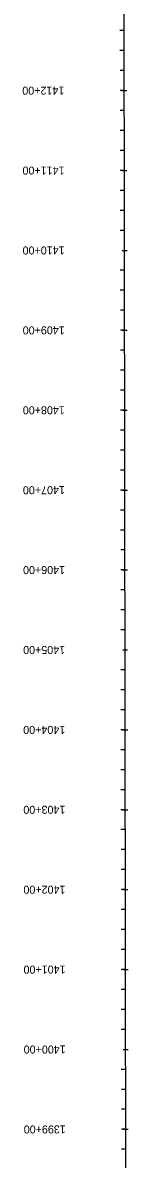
# Model space of a CAD drawing. Extents: x 14541681 to 14544384, y 8572153 to 8583558.
# Drawn here: x 14541682 to 14541814, y 8580711 to 8582134 of the extents above; entities that cross this region are included whole.
import ezdxf

# ---------------------------------------------------------------- set-up
doc = ezdxf.new("R2010")
doc.units = 0
for name, color, linetype in [('Alignment', 7, 'Continuous'), ('TextAlignmentLrg', 7, 'Continuous'), ('TextAlignmentSml', 7, 'Continuous')]:
    doc.layers.add(name, color=color, linetype=linetype)

msp = doc.modelspace()

# ---------------------------------------------------------------- linework, layer by layer
at = {"layer": 'Alignment'}
msp.add_line((14541811.5, 8580543.1), (14541807.4, 8583548.8), dxfattribs=at)
at = {"layer": 'TextAlignmentLrg'}
for p, q in [((14541809.5, 8582048.8), (14541804, 8582048.8)), ((14541809.6, 8581948.8), (14541804.1, 8581948.8)), ((14541806.7, 8581848.8), (14541812.8, 8581848.8)), ((14541809.9, 8581748.8), (14541804.4, 8581748.8)), ((14541810, 8581648.8), (14541804.5, 8581648.8)), ((14541810.1, 8581548.8), (14541804.7, 8581548.8)), ((14541810.3, 8581448.8), (14541804.8, 8581448.8)), ((14541807.3, 8581348.8), (14541813.5, 8581348.8)), ((14541810.5, 8581248.8), (14541805.1, 8581248.8)), ((14541810.7, 8581148.8), (14541805.2, 8581148.8)), ((14541810.8, 8581048.8), (14541805.3, 8581048.8)), ((14541810.9, 8580948.8), (14541805.5, 8580948.8)), ((14541808, 8580848.8), (14541814.1, 8580848.8)), ((14541811.2, 8580748.8), (14541805.7, 8580748.8))]:
    msp.add_line(p, q, dxfattribs=at)
at = {"layer": 'TextAlignmentSml'}
for p, q in [((14541809.4, 8582123.8), (14541803.9, 8582123.8)), ((14541809.4, 8582098.8), (14541803.9, 8582098.8)), ((14541809.4, 8582073.8), (14541804, 8582073.8)), ((14541806.4, 8582048.8), (14541812.5, 8582048.8)), ((14541809.5, 8582023.8), (14541804, 8582023.8)), ((14541809.5, 8581998.8), (14541804.1, 8581998.8)), ((14541809.6, 8581973.8), (14541804.1, 8581973.8)), ((14541806.5, 8581948.8), (14541812.6, 8581948.8)), ((14541809.6, 8581923.8), (14541804.2, 8581923.8)), ((14541809.7, 8581898.8), (14541804.2, 8581898.8)), ((14541809.7, 8581873.8), (14541804.2, 8581873.8)), ((14541806.7, 8581848.8), (14541812.8, 8581848.8)), ((14541809.8, 8581823.8), (14541804.3, 8581823.8)), ((14541809.8, 8581798.8), (14541804.3, 8581798.8)), ((14541809.8, 8581773.8), (14541804.4, 8581773.8)), ((14541806.8, 8581748.8), (14541812.9, 8581748.8)), ((14541809.9, 8581723.8), (14541804.4, 8581723.8)), ((14541809.9, 8581698.8), (14541804.5, 8581698.8)), ((14541810, 8581673.8), (14541804.5, 8581673.8)), ((14541806.9, 8581648.8), (14541813.1, 8581648.8)), ((14541810, 8581623.8), (14541804.6, 8581623.8)), ((14541810.1, 8581598.8), (14541804.6, 8581598.8)), ((14541810.1, 8581573.8), (14541804.6, 8581573.8)), ((14541807.1, 8581548.8), (14541813.2, 8581548.8)), ((14541810.2, 8581523.8), (14541804.7, 8581523.8)), ((14541810.2, 8581498.8), (14541804.7, 8581498.8)), ((14541810.2, 8581473.8), (14541804.8, 8581473.8)), ((14541807.2, 8581448.8), (14541813.3, 8581448.8)), ((14541810.3, 8581423.8), (14541804.8, 8581423.8)), ((14541810.3, 8581398.8), (14541804.9, 8581398.8)), ((14541810.4, 8581373.8), (14541804.9, 8581373.8)), ((14541807.3, 8581348.8), (14541813.5, 8581348.8)), ((14541810.4, 8581323.8), (14541805, 8581323.8)), ((14541810.5, 8581298.8), (14541805, 8581298.8)), ((14541810.5, 8581273.8), (14541805, 8581273.8)), ((14541807.5, 8581248.8), (14541813.6, 8581248.8)), ((14541810.6, 8581223.8), (14541805.1, 8581223.8)), ((14541810.6, 8581198.8), (14541805.1, 8581198.8)), ((14541810.6, 8581173.8), (14541805.2, 8581173.8)), ((14541807.6, 8581148.8), (14541813.7, 8581148.8)), ((14541810.7, 8581123.8), (14541805.2, 8581123.8)), ((14541810.7, 8581098.8), (14541805.3, 8581098.8)), ((14541810.8, 8581073.8), (14541805.3, 8581073.8)), ((14541807.7, 8581048.8), (14541813.9, 8581048.8)), ((14541810.8, 8581023.8), (14541805.4, 8581023.8)), ((14541810.9, 8580998.8), (14541805.4, 8580998.8)), ((14541810.9, 8580973.8), (14541805.4, 8580973.8)), ((14541807.9, 8580948.8), (14541814, 8580948.8)), ((14541811, 8580923.8), (14541805.5, 8580923.8)), ((14541811, 8580898.8), (14541805.5, 8580898.8)), ((14541811, 8580873.8), (14541805.6, 8580873.8)), ((14541808, 8580848.8), (14541814.1, 8580848.8)), ((14541811.1, 8580823.8), (14541805.6, 8580823.8)), ((14541811.1, 8580798.8), (14541805.7, 8580798.8)), ((14541811.2, 8580773.8), (14541805.7, 8580773.8)), ((14541808.1, 8580748.8), (14541814.3, 8580748.8)), ((14541811.2, 8580723.8), (14541805.8, 8580723.8))]:
    msp.add_line(p, q, dxfattribs=at)

# ---------------------------------------------------------------- texts
at = {"layer": 'TextAlignmentLrg'}
for s, p in [('1410+00', (14541734.7, 8581853.7)), ('1405+00', (14541735.4, 8581353.7)), ('1400+00', (14541736.1, 8580853.7))]:
    msp.add_text(s, height=10.02, rotation=180.077, dxfattribs=at).set_placement(p)
at = {"layer": 'TextAlignmentSml'}
for s, p in [('1412+00', (14541734.4, 8582053.7)), ('1411+00', (14541734.6, 8581953.7)), ('1410+00', (14541734.7, 8581853.7)), ('1409+00', (14541734.9, 8581753.7)), ('1408+00', (14541735, 8581653.7)), ('1407+00', (14541735.1, 8581553.7)), ('1406+00', (14541735.3, 8581453.7)), ('1405+00', (14541735.4, 8581353.7)), ('1404+00', (14541735.5, 8581253.7)), ('1403+00', (14541735.7, 8581153.7)), ('1402+00', (14541735.8, 8581053.7)), ('1401+00', (14541735.9, 8580953.7)), ('1400+00', (14541736.1, 8580853.7)), ('1399+00', (14541736.2, 8580753.7))]:
    msp.add_text(s, height=10.02, rotation=180.077, dxfattribs=at).set_placement(p)

doc.saveas('drawing.dxf')
